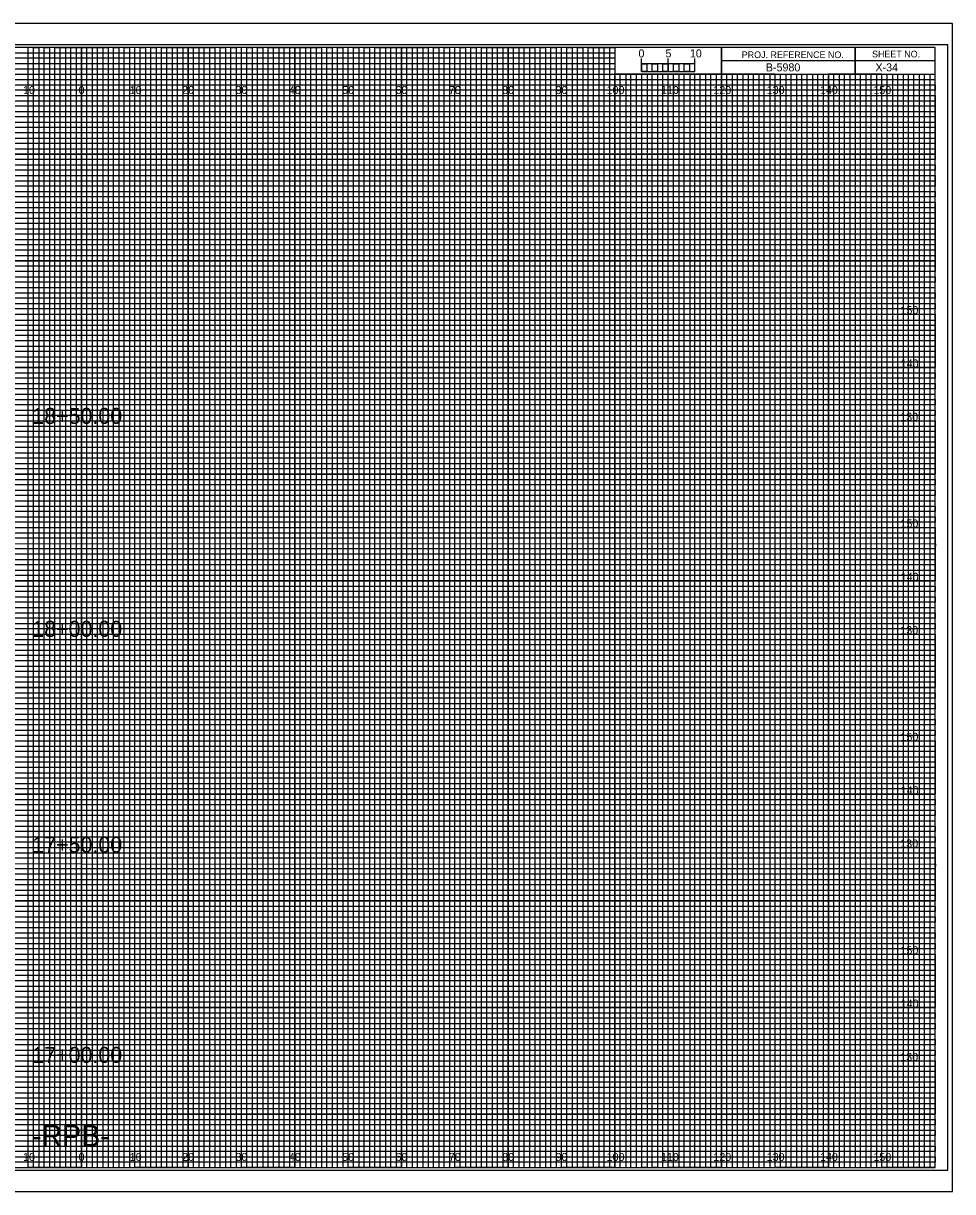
# Model space of a CAD drawing. Extents: x -13 to 323, y -5 to 1094.
# Drawn here: x 149.1 to 323.3, y 215.5 to 434.5 of the extents above; entities that cross this region are included whole.
import ezdxf

# ---------------------------------------------------------------- set-up
doc = ezdxf.new("R2010")
doc.units = 0
for name, color, linetype in [('Exist Cross Section Cell', 7, 'Continuous'), ('Exist XS Center Line Elevation Label', 7, 'Continuous'), ('Exist XS Ground Line', 7, 'Continuous'), ('Prop CMT Concrete Structures', 7, 'Continuous'), ('Prop CMT Guardrail Graphics', 7, 'Continuous'), ('Prop CMT Pvmt Course 1', 7, 'Continuous'), ('Prop CMT Pvmt Course 1 CG', 7, 'Continuous'), ('Prop CMT Pvmt Course 2', 7, 'Continuous'), ('Prop CMT Pvmt Course 3', 7, 'Continuous'), ('Prop CMT Pvmt Surface', 7, 'Continuous'), ('Prop CMT Pvmt Surface Shoulder', 7, 'Continuous'), ('Prop CMT Shld Paved Course 1', 7, 'Continuous'), ('Prop CMT Shld Paved Course 2', 7, 'Continuous'), ('Prop CMT Shld Paved Course 3', 7, 'Continuous'), ('Prop CMT Slope Grass', 7, 'Continuous'), ('Prop CMT Subgrade Earthwork', 7, 'Continuous'), ('Scratch_Level_1', 7, 'Continuous')]:
    doc.layers.add(name, color=color, linetype=linetype)

msp = doc.modelspace()

# ---------------------------------------------------------------- linework, layer by layer
at = {"layer": 'Exist XS Center Line Elevation Label'}
for points in [[(145, 220), (155, 220), (155, 430), (165, 430), (165, 220), (175, 220), (175, 430), (185, 430), (185, 220), (195, 220), (195, 430), (205, 430), (205, 220), (215, 220), (215, 430), (225, 430), (225, 220), (235, 220), (235, 430), (245, 430), (245, 220), (255, 220), (255, 430), (259.93, 430), (260, 430), (260, 425), (264.99, 425), (264.99, 220), (275, 220), (275, 425), (285, 425), (285, 220), (295, 220), (295, 425), (305, 425), (305, 220), (315, 220), (315, 425)], [(0, 425), (275, 425)], [(0, 405), (320, 405), (320, 415), (0, 415)], [(0, 385), (320, 385), (320, 395), (0, 395)], [(0, 365), (320, 365), (320, 375), (0, 375)], [(0, 345), (320, 345), (320, 355), (0, 355)], [(0, 325), (320, 325), (320, 335), (0, 335)], [(0, 305), (320, 305), (320, 315), (0, 315)], [(0, 285), (320, 285), (320, 295), (0, 295)], [(0, 265), (320, 265), (320, 275), (0, 275)], [(0, 245), (320, 245), (320, 255), (0, 255)], [(0, 225), (320, 225), (320, 235), (0, 235)]]:
    msp.add_lwpolyline(points, dxfattribs=at)
at = {"layer": 'Exist XS Ground Line'}
for p, q in [((150, 430), (140, 430)), ((150, 220), (150, 430)), ((170, 430), (160, 430)), ((160, 430), (160, 220)), ((170, 220), (170, 430)), ((190, 430), (180, 430)), ((180, 430), (180, 220)), ((190, 220), (190, 430)), ((210, 430), (200, 430)), ((200, 430), (200, 220)), ((210, 220), (210, 430)), ((230, 430), (220, 430)), ((220, 430), (220, 220)), ((230, 220), (230, 430)), ((250, 430), (240, 430)), ((240, 430), (240, 220)), ((250, 220), (250, 430)), ((260, 430), (260, 220)), ((270, 220), (270, 425)), ((290, 425), (280, 425)), ((280, 425), (280, 220)), ((290, 220), (290, 425)), ((310, 425), (300, 425)), ((300, 425), (300, 220)), ((310, 220), (310, 425)), ((160, 220), (150, 220)), ((180, 220), (170, 220)), ((200, 220), (190, 220)), ((220, 220), (210, 220)), ((240, 220), (230, 220)), ((260, 220), (250, 220)), ((280, 220), (270, 220)), ((300, 220), (290, 220)), ((320, 220), (310, 220)), ((320, 220), (320, 220))]:
    msp.add_line(p, q, dxfattribs=at)
for points in [[(0, 420), (320, 420), (320, 410), (0, 410)], [(0, 400), (320, 400), (320, 390), (0, 390)], [(0, 380), (320, 380), (320, 370), (0, 370)], [(0, 360), (320, 360), (320, 350), (0, 350)], [(0, 340), (320, 340), (320, 330), (0, 330)], [(0, 320), (320, 320), (320, 310), (0, 310)], [(0, 300), (320, 300), (320, 290), (0, 290)], [(0, 280), (320, 280), (320, 270), (0, 270)], [(0, 260), (320, 260), (320, 250), (0, 250)], [(0, 240), (320, 240), (320, 230), (0, 230)]]:
    msp.add_lwpolyline(points, dxfattribs=at)
at = {"layer": 'Prop CMT Pvmt Course 2'}
for p, q in [((265, 425.49), (265, 427.9)), ((265, 426.9), (265, 427.9)), ((270, 425.49), (270, 427.9)), ((275, 425.49), (275, 427.9)), ((275, 426.9), (275, 427.9))]:
    msp.add_line(p, q, dxfattribs=at)
for points in [[(275, 426.9), (265, 426.9), (265, 425.49), (275, 425.49)], [(265, 426.9), (266, 426.9), (266, 425.49), (265, 425.49)], [(267, 426.9), (268, 426.9), (268, 425.49), (267, 425.49)], [(269, 426.9), (270, 426.9), (270, 425.49), (269, 425.49)], [(271, 426.9), (272, 426.9), (272, 425.49), (271, 425.49)], [(273, 426.9), (274, 426.9), (274, 425.49), (273, 425.49)]]:
    msp.add_lwpolyline(points, close=True, dxfattribs=at)
at = {"layer": 'Prop CMT Pvmt Course 3'}
msp.add_lwpolyline([(-13.4, 215.5), (323.3, 215.5), (323.3, 434.5), (-13.4, 434.5)], close=True, dxfattribs=at)
at = {"layer": 'Prop CMT Pvmt Surface'}
for p, q in [((150, 220), (150, 430)), ((160, 220), (160, 430)), ((170, 220), (170, 430)), ((180, 220), (180, 430)), ((190, 220), (190, 430)), ((200, 220), (200, 430)), ((210, 220), (210, 430)), ((220, 220), (220, 430)), ((230, 220), (230, 430)), ((240, 220), (240, 430)), ((250, 220), (250, 430)), ((260, 220), (260, 424.69)), ((270, 220), (270, 424.69)), ((280, 220), (280, 424.69)), ((290, 220), (290, 424.69)), ((300, 220), (300, 424.69)), ((310, 220), (310, 424.69)), ((0, 420), (320, 420)), ((0, 410), (320, 410)), ((0, 400), (320, 400)), ((0, 390), (320, 390)), ((0, 380), (320, 380)), ((0, 370), (320, 370)), ((0, 360), (320, 360)), ((0, 350), (320, 350)), ((0, 340), (320, 340)), ((0, 330), (320, 330)), ((0, 320), (320, 320)), ((0, 310), (320, 310)), ((0, 300), (320, 300)), ((0, 290), (320, 290)), ((0, 280), (320, 280)), ((0, 270), (320, 270)), ((0, 260), (320, 260)), ((0, 250), (320, 250)), ((0, 240), (320, 240)), ((0, 230), (320, 230))]:
    msp.add_line(p, q, dxfattribs=at)
at = {"layer": 'Prop CMT Pvmt Surface Shoulder'}
for p, q in [((323.3, 434.5), (-13.4, 434.5)), ((-13.4, 215.5), (323.3, 215.5))]:
    msp.add_line(p, q, dxfattribs=at)
at = {"layer": 'Prop CMT Shld Paved Course 1'}
for p, q in [((0, 429), (260, 429)), ((260, 427.98), (0, 427.98)), ((260, 429), (260, 427.98)), ((0, 427), (260, 427)), ((260, 425.89), (0, 425.89)), ((260, 427), (260, 425.89)), ((0, 424), (320, 424))]:
    msp.add_line(p, q, dxfattribs=at)
for points in [[(0, 423), (270, 423), (320, 423), (320, 422), (0, 422)], [(0, 421), (320, 421), (320, 419), (0, 419)], [(0, 418), (320, 418), (320, 417), (0, 416.98)], [(0, 416), (320, 416), (320, 414), (0, 414)], [(0, 413), (320, 413), (320, 412), (0, 412)], [(0, 411), (320, 411), (320, 409), (0, 409)], [(0, 408), (320, 408), (320, 407), (0, 407)], [(0, 406), (320, 406), (320, 404), (0, 404)], [(0, 403), (320, 403), (320, 402), (0, 402)], [(0, 401), (320, 401), (320, 399), (0, 399)], [(0, 398), (320, 398), (320, 397), (0, 397)], [(0, 396), (320, 396), (320, 393.95), (320, 393), (320, 392), (0, 392)], [(0, 394), (320, 394), (320, 393), (0, 393)], [(0, 391), (320, 391), (320, 389), (0, 389.03)], [(0, 389.03), (320, 389), (320, 388), (0, 388)], [(0, 387), (320, 387), (320, 386), (0, 386)], [(0, 384), (320, 384), (320, 383), (0, 383)], [(0, 382), (320, 382), (320, 381), (0, 381)], [(-0.07, 378.89), (320, 378.89), (320, 377.88), (-0.07, 377.88)], [(0, 377), (320, 377), (320, 376), (0, 376)], [(0, 374), (320, 374), (320, 373), (0, 373)], [(0, 372), (320, 372), (320, 371), (0, 371)], [(0, 369), (320, 369), (320, 368), (0, 368)], [(0, 367), (320, 367), (320, 366), (0, 366)], [(0, 364), (320, 364), (320, 363), (0, 363)], [(0, 362), (320, 362), (320, 361), (0, 361)], [(0, 359), (320, 359), (319.99, 357.98), (0, 358)], [(0, 357), (320, 357), (320, 356), (0, 356)], [(0, 354), (320, 354), (320, 353), (0, 353)], [(0, 352), (320, 352), (320, 351), (0, 351)], [(0, 349), (320, 349), (320, 348), (0, 348)], [(0, 347), (320, 347), (320, 346), (0, 346)], [(0, 344), (320, 344), (320, 343), (0, 343)], [(0, 342), (320, 342), (320, 341), (0, 341)], [(0, 339), (320, 339), (320, 338), (0, 338)], [(0, 336.99), (320.07, 336.91), (320, 336), (0, 336)], [(0, 334), (320, 334), (320, 333), (0, 333)], [(0, 332), (320, 332), (320, 331), (0, 331)], [(0, 329), (320, 329), (320, 328), (0, 328)], [(0, 327), (320, 327), (320, 326), (0, 326)], [(0, 324), (320, 324), (320, 323), (0, 323)], [(0, 322), (320, 322), (320, 321), (0, 321)], [(0, 319), (320, 319), (320, 318), (0, 318)], [(0, 317), (320, 317), (320, 316), (0, 316)], [(0, 314), (320, 314), (320, 313), (0, 313)], [(0, 312), (320, 312), (320, 311), (0, 311)], [(0, 309), (320, 309), (320, 308), (0, 308)], [(0, 307), (320, 307), (320, 306), (0, 306)], [(0, 304), (320, 304), (320, 303), (0, 303)], [(0, 302), (320, 302), (320, 301), (0, 301)], [(0, 299), (320, 299), (319.99, 297.98), (0, 298)], [(0, 297), (320, 297), (320, 296), (0, 296)], [(0, 294), (320, 294), (320, 293), (0, 293)], [(0, 292), (320, 292), (320, 291), (0, 291)], [(0, 289), (320, 289), (320, 288), (0, 288)], [(0, 287), (320, 287), (320, 286), (0, 286)], [(0, 284), (320, 284), (320, 283), (0, 283)], [(0, 282), (320, 282), (320, 281), (0, 281)], [(0, 279), (320, 279), (320, 278), (0, 278)], [(0, 276.99), (320.07, 276.91), (320, 276), (0, 276)], [(0, 274), (320, 274), (320, 273), (0, 273)], [(0, 272), (320, 272), (320, 271), (0, 271)], [(0, 269), (320, 269), (320, 268), (0, 268)], [(0, 267), (320, 267), (320, 266), (0, 266)], [(0, 264), (320, 264), (320, 263), (0, 263)], [(0, 262), (320, 262), (320, 261), (0, 261)], [(0, 259), (320, 259), (320, 258), (0, 258)], [(0, 257), (320, 257), (320, 256), (0, 256)], [(0, 254), (320, 254), (320, 253), (0, 253)], [(0, 252), (320, 252), (320, 251), (0, 251)], [(0, 249), (320, 249), (320, 248), (0, 248)], [(0, 247), (320, 247), (320, 246), (0, 246)], [(0, 244), (320, 244), (320, 243), (0, 243)], [(0, 242), (320, 242), (320, 241), (0, 241)], [(0, 239), (320, 239), (320, 238), (0, 238)], [(0, 237), (320, 237), (320, 236), (0, 236)], [(0, 234), (320, 234), (320, 233), (0, 233)], [(0, 232), (320, 232), (320, 231), (0, 231)], [(0, 229), (320, 229), (320, 228), (0, 228)], [(0, 227), (320, 227), (320, 226), (0, 226)], [(0, 224), (320, 224), (320, 223), (0, 223)], [(0, 222), (320, 222), (320, 221), (0, 221)]]:
    msp.add_lwpolyline(points, dxfattribs=at)
at = {"layer": 'Prop CMT Shld Paved Course 2'}
for p, q in [((305, 430), (305, 425)), ((305, 425), (305, 430)), ((280, 427.5), (280, 425)), ((320, 427.49), (280, 427.49)), ((280, 425), (320, 425))]:
    msp.add_line(p, q, dxfattribs=at)
for points in [[(320, 430), (0, 430), (0, 220), (320, 220)], [(280, 430), (260, 430), (260, 425.03), (280, 425.03)], [(320, 430), (280, 430), (280, 425), (320, 425)]]:
    msp.add_lwpolyline(points, close=True, dxfattribs=at)
at = {"layer": 'Prop CMT Shld Paved Course 3'}
for p, q in [((267, 425), (266.01, 425)), ((266.01, 425), (266.01, 220)), ((267, 220), (267, 425)), ((269, 425), (268, 425)), ((268, 425), (268, 220)), ((269, 220), (269, 425)), ((266.01, 220), (265, 220)), ((268, 220), (267, 220))]:
    msp.add_line(p, q, dxfattribs=at)
for points in [[(150, 220), (151, 220), (151, 430), (152, 430), (152, 220)], [(152, 220), (153, 220), (153, 430), (154, 430), (154, 220)], [(155, 220), (156, 220), (156, 430), (157, 430), (157, 220)], [(157, 220), (158, 220), (158, 430), (159, 430), (159, 220)], [(160, 220), (161, 220), (161, 430), (162, 430), (162, 220)], [(162, 220), (163, 220), (163, 430), (164, 430), (164, 220)], [(165, 220), (166, 220), (166, 430), (167, 430), (167, 220)], [(167, 220), (168, 220), (168, 430), (169, 430), (169, 220)], [(170, 220), (171, 220), (171, 430), (172, 430), (172, 220)], [(172, 220), (173, 220), (173, 430), (174, 430), (174, 220)], [(175, 220), (176, 220), (176, 430), (177, 430), (177, 220)], [(177, 220), (178, 220), (178, 430), (179, 430), (179, 220)], [(180, 220), (181, 220), (181, 430), (182, 430), (182, 220)], [(182, 220), (183, 220), (183, 430), (184, 430), (184, 220)], [(185, 220), (186, 220), (186, 430), (187, 430), (187, 220)], [(187, 220), (188, 220), (188, 430), (189, 430), (189, 220)], [(190, 220), (191, 220), (191, 430), (192, 430), (192, 220)], [(192, 220), (193, 220), (193, 430), (194, 430), (194, 220)], [(195, 220), (196, 220), (196, 430), (197, 430), (197, 220)], [(197, 220), (198, 220), (198, 430), (199, 430), (199, 220)], [(200, 220), (201, 220), (201, 430), (202, 430), (202, 220)], [(202, 220), (203, 220), (203, 430), (204, 430), (204, 220)], [(205, 220), (206, 220), (206, 430), (207, 430), (207, 220)], [(207, 220), (208, 220), (208, 430), (209, 430), (209, 220)], [(210, 220), (211, 220), (211, 430), (212, 430), (212, 220)], [(212, 220), (213, 220), (213, 430), (214, 430), (214, 220)], [(215, 220), (216, 220), (216, 430), (217, 430), (217, 220)], [(217, 220), (218, 220), (218, 430), (219, 430), (219, 220)], [(220, 220), (221, 220), (221, 430), (222, 430), (222, 220)], [(222, 220), (223, 220), (223, 430), (224, 430), (224, 220)], [(225, 220), (226, 220), (226, 430), (227, 430), (227, 220)], [(227, 220), (228, 220), (228, 430), (229, 430), (229, 220)], [(230, 220), (231, 220), (231, 430), (232, 430), (232, 220)], [(232, 220), (233, 220), (233, 430), (234, 430), (234, 220)], [(235, 220), (236, 220), (236, 430), (237, 430), (237, 220)], [(237, 220), (238, 220), (238, 430), (239, 430), (239, 220)], [(240, 220), (241, 220), (241, 430), (242, 430), (242, 220)], [(242, 220), (243, 220), (243, 430), (244, 430), (244, 220)], [(245, 220), (246, 220), (246, 430), (247, 430), (247, 220)], [(247, 220), (248, 220), (248, 430), (249, 430), (249, 220)], [(250, 220), (251, 220), (251, 430), (252, 430), (252, 220)], [(252, 220), (253, 220), (253, 430), (254, 430), (254, 220)], [(255, 220), (256, 220), (256, 430), (257, 430), (257, 220)], [(257, 220), (258, 220), (258, 430), (259, 430), (259, 220)], [(260, 220), (261, 220), (261, 425), (262.02, 425), (262.02, 220)], [(262, 220), (263, 220), (263, 425), (263.99, 425), (263.99, 220)], [(270, 220), (270.98, 220), (270.98, 425), (272, 425), (272, 220)], [(272, 220), (273, 220), (273, 425), (274.05, 425), (274.05, 220)], [(275, 220), (276, 220), (276, 425), (277, 425), (277, 220)], [(277, 220), (278, 220), (278, 425), (279, 425), (279, 220)], [(280, 220), (281, 220), (281, 425), (282, 425), (282, 220)], [(282, 220), (283, 220), (283, 425), (284, 425), (284, 220)], [(285, 220), (286, 220), (286, 425), (287, 425), (287, 220)], [(287, 220), (288, 220), (288, 425), (289, 425), (289, 220)], [(290, 220), (291, 220), (291, 425), (292, 425), (292, 220)], [(292, 220), (293, 220), (293, 425), (294, 425), (294, 220)], [(295, 220), (296, 220), (296, 425), (297, 425), (297, 220)], [(297, 220), (298, 220), (298, 425), (299, 425), (299, 220)], [(300, 220), (301, 220), (301, 425), (302, 425), (302, 220)], [(302, 220), (303, 220), (303, 425), (304, 425), (304, 220)], [(305, 220), (306, 220), (306, 425), (307, 425), (307, 220)], [(307, 220), (308, 220), (308, 425), (309, 425), (309, 220)], [(310, 220), (311, 220), (311, 425), (312, 425), (312, 220)], [(312, 220), (313, 220), (313, 425), (314, 425), (314, 220)], [(315, 220), (316, 220), (316, 425), (317, 425), (317, 220)], [(317, 220), (318, 220), (318, 425), (319, 425), (319, 220)]]:
    msp.add_lwpolyline(points, dxfattribs=at)
at = {"layer": 'Prop CMT Subgrade Earthwork'}
msp.add_lwpolyline([(-10.8, 219.5), (322.4, 219.5), (322.4, 430.5), (-10.8, 430.5)], close=True, dxfattribs=at)

# ---------------------------------------------------------------- texts
at = {"layer": 'Exist Cross Section Cell'}
for s, p in [('10', (149.04, 421.25)), ('0', (159.45, 421.25)), ('0', (159.45, 421.25)), ('10', (169.04, 421.25)), ('20', (178.86, 421.25)), ('30', (188.86, 421.25)), ('40', (198.86, 421.25)), ('50', (208.86, 421.25)), ('60', (218.86, 421.25)), ('70', (228.86, 421.25)), ('80', (238.86, 421.25)), ('90', (248.86, 421.25)), ('100', (258.44, 421.25)), ('110', (268.62, 421.25)), ('120', (278.44, 421.25)), ('130', (288.44, 421.25)), ('140', (298.44, 421.25)), ('150', (308.44, 421.25)), ('10', (149.04, 221.25)), ('0', (159.45, 221.25)), ('0', (159.45, 221.25)), ('10', (169.04, 221.25)), ('20', (178.86, 221.25)), ('30', (188.86, 221.25)), ('40', (198.86, 221.25)), ('50', (208.86, 221.25)), ('60', (218.86, 221.25)), ('70', (228.86, 221.25)), ('80', (238.86, 221.25)), ('90', (248.86, 221.25)), ('100', (258.44, 221.25)), ('110', (268.62, 221.25)), ('120', (278.44, 221.25)), ('130', (288.44, 221.25)), ('140', (298.44, 221.25)), ('150', (308.44, 221.25))]:
    msp.add_text(s, height=1.5, dxfattribs=at).set_placement(p)
at = {"layer": 'Prop CMT Concrete Structures'}
msp.add_text('-RPB-', height=4, dxfattribs=at).set_placement((150.72, 224))
at = {"layer": 'Prop CMT Guardrail Graphics'}
msp.add_text('X-34', height=1.5, dxfattribs=at).set_placement((308.83, 425.5))
at = {"layer": 'Prop CMT Pvmt Course 1'}
for s, p in [('150', (313.52, 380)), ('140', (313.57, 370)), ('130', (313.49, 360)), ('150', (313.52, 340)), ('140', (313.57, 330)), ('130', (313.49, 320)), ('150', (313.52, 300)), ('140', (313.57, 290)), ('130', (313.49, 280)), ('150', (313.52, 260)), ('140', (313.57, 250)), ('130', (313.49, 240))]:
    msp.add_text(s, height=1.5, dxfattribs=at).set_placement(p)
at = {"layer": 'Prop CMT Pvmt Course 1 CG'}
for s, p in [('5', (269.47, 428.12)), ('10', (274.04, 428.12))]:
    msp.add_text(s, height=1.5, dxfattribs=at).set_placement(p)
at = {"layer": 'Prop CMT Pvmt Course 2'}
msp.add_text('0', height=1.5, dxfattribs=at).set_placement((264.41, 428.12))
at = {"layer": 'Prop CMT Shld Paved Course 2'}
for s, p in [('PROJ. REFERENCE NO.', (283.77, 427.99)), ('SHEET NO.', (308.19, 428.12))]:
    msp.add_text(s, height=1.25, dxfattribs=at).set_placement(p)
at = {"layer": 'Prop CMT Slope Grass'}
for s, p in [('18+50.00', (150.77, 359.42)), ('18+00.00', (150.77, 319.5)), ('17+50.00', (150.77, 279.04)), ('17+00.00', (150.77, 239.63))]:
    msp.add_text(s, height=3, dxfattribs=at).set_placement(p)
at = {"layer": 'Scratch_Level_1'}
msp.add_text('B-5980', height=1.5, dxfattribs=at).set_placement((288.28, 425.5))

doc.saveas('drawing.dxf')
